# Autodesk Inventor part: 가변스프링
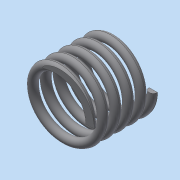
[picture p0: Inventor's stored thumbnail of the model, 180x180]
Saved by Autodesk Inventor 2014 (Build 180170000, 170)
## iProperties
Created: 2026-06
Part Number: 가변스프링
Material: 일반
Document SubType Name: Modeling
Designer: dg
Density: 1 g/cm^3
Appearance: 기본값
Author: dg
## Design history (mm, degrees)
sketch "스케치1"
  geometry: L1 (0, 0)-(7.5, 0); L2 (0, 0)-(0, 23); L3 (0, 23)-(5.76, 23); C1 r 1 at (7.5, 0)
  constraints: 6 end point, 2 horizontal, 1 centre point, 1 coincident, 1 perpendicular
  dimensions: "d0" = 15 diameter of L1.end L2; "d1" = 2 diameter of C1; "d2" = 23 distance from line of L3 L1.end (derived)
feature "코일1" sketch "스케치1" pitch "d3" = 10; turns "d5" = 5; dims "d4" = 23 (= d2), "d6" = 0, angle "d7" = 90 deg, angle "d8" = 90 deg, "d9" = 0, "d10" = 0
node "작업 평면1"
feature "분할1"
feature "분할2"
node "솔리드1"
other parameters: "d11" = 0
